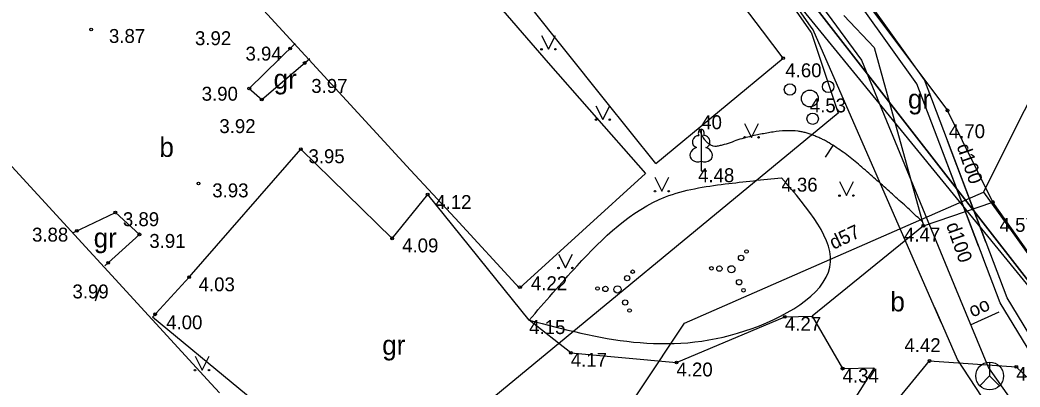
# Model space of a CAD drawing. Extents: x 519536 to 519949, y 326041 to 326519.
# Drawn here: x 519801.93 to 519837.87, y 326233.27 to 326246.46 of the extents above; entities that cross this region are included whole.
import ezdxf

# ---------------------------------------------------------------- set-up
doc = ezdxf.new("R2010")
doc.units = 0
for name, color, linetype in [('APGR_SARK_####_####_#', 7, 'Continuous'), ('BUVE_EKAS_####_####_#', 7, 'Continuous'), ('CELI_CMAL_####_####_#', 7, 'Continuous'), ('CELI_CSEG_####_TKST_#', 7, 'Continuous'), ('CELI_SEGL_####_####_#', 7, 'Continuous'), ('ELEK_ACRL_####_####_#', 7, 'Continuous'), ('ELEK_ACRL_####_TKST_#', 7, 'Continuous'), ('ELEK_VADP_ZSPR_####_#', 7, 'Continuous'), ('GAZE_VADP_ASP1_####_#', 7, 'Continuous'), ('GAZE_VADP_NEDR_####_#', 7, 'Continuous'), ('GAZE_VADP_NEDR_TKST_#', 7, 'Continuous'), ('RELJ_AATZ_####_TKST_#', 7, 'Continuous'), ('RELJ_ELEM_####_####_#', 7, 'Continuous'), ('RELJ_HORZ_PAMT_####_#', 7, 'Continuous'), ('ROBZ_PROJ_####_####_#', 7, 'Continuous'), ('ROBZ_UZMR_####_####_#', 7, 'Continuous'), ('SAKK_ELEM_####_####_#', 7, 'Continuous'), ('SAKK_IZVK_####_TKST_#', 7, 'Continuous'), ('SAKK_KKAN_####_####_#', 7, 'Continuous'), ('TERT_DIAM_####_TKST_#', 7, 'Continuous'), ('TERT_ELEM_####_####_#', 7, 'Continuous'), ('TERT_KONT_####_####_#', 7, 'Continuous')]:
    doc.layers.add(name, color=color, linetype=linetype)

msp = doc.modelspace()

# ---------------------------------------------------------------- linework, layer by layer
at = {"layer": 'APGR_SARK_####_####_#'}
msp.add_line((519771.502, 326318.577), (519839.505, 326235.263), dxfattribs=at)
at = {"layer": 'BUVE_EKAS_####_####_#'}
msp.add_line((519819.879, 326236.819), (519824.406, 326240.947), dxfattribs=at)
for points in [[(519815.97, 326241.067), (519794.322, 326264.64), (519799.853, 326269.244)], [(519799.853, 326269.244), (519820.912, 326244.923)], [(519821.513, 326245.392), (519802.904, 326268.709)], [(519808.8, 326233.381), (519787.845, 326256.231), (519782.307, 326251.018)], [(519828.616, 326246.073), (519826.305, 326249.13)], [(519824.78, 326241.299), (519829.361, 326245.088), (519828.616, 326246.073)], [(519822.941, 326243.604), (519821.513, 326245.392)], [(519820.912, 326244.923), (519822.387, 326243.244)], [(519824.78, 326241.299), (519822.941, 326243.604)], [(519822.387, 326243.244), (519824.406, 326240.947)], [(519817.566, 326239.333), (519815.97, 326241.067)], [(519819.879, 326236.819), (519817.566, 326239.333)], [(519809.102, 326233.051), (519808.8, 326233.381)]]:
    msp.add_lwpolyline(points, dxfattribs=at)
at = {"layer": 'CELI_CMAL_####_####_#'}
for p, q in [((519831.546, 326246.618), (519832.626, 326245.477)), ((519811.824, 326245.617), (519810.171, 326243.995)), ((519810.617, 326243.606), (519812.348, 326245.072)), ((519810.171, 326243.995), (519810.617, 326243.606)), ((519808.01, 326237.212), (519812.026, 326241.818)), ((519812.026, 326241.818), (519815.308, 326238.61)), ((519815.308, 326238.61), (519816.583, 326240.187)), ((519803.858, 326238.824), (519805.357, 326239.536)), ((519805.357, 326239.536), (519806.221, 326238.754)), ((519806.221, 326238.754), (519804.98, 326237.626)), ((519806.695, 326235.774), (519808.01, 326237.212))]:
    msp.add_line(p, q, dxfattribs=at)
for points in [[(519797.68, 326294.786), (519803.307, 326287.694), (519809.593, 326279.318), (519814.875, 326272.28), (519822.676, 326261.61), (519829.759, 326251.994), (519832.548, 326246.837), (519835.264, 326243.212)], [(519832.626, 326245.477), (519834.4, 326239.065)], [(519882.222, 326178.789), (519878.977, 326182.88), (519874.995, 326188.433), (519867.888, 326197.765), (519858.139, 326210.779), (519849.58, 326222.15), (519841.494, 326233.418), (519836.895, 326239.916), (519835.264, 326243.212)], [(519821.726, 326234.491), (519820.231, 326235.669), (519816.583, 326240.187)], [(519834.4, 326239.065), (519830.403, 326235.818), (519831.497, 326233.926), (519832.631, 326233.959), (519830.408, 326230.433), (519831.453, 326230.348), (519834.622, 326234.201), (519837.739, 326233.988), (519838.727, 326233.045), (519840.51, 326232.736), (519841.494, 326233.418)], [(519802.986, 326218.602), (519812.095, 326226.609), (519812.9, 326230.644), (519806.695, 326235.774)], [(519821.726, 326234.491), (519825.526, 326234.144), (519829.423, 326235.788), (519830.403, 326235.818)]]:
    msp.add_lwpolyline(points, dxfattribs=at)
at = {"layer": 'CELI_SEGL_####_####_#'}
msp.add_lwpolyline([(519834.4, 326239.065), (519836.895, 326239.916)], dxfattribs=at)
at = {"layer": 'ELEK_ACRL_####_####_#'}
for p, q in [((519834.982, 326242.008), (519836.373, 326238.339)), ((519836.644, 326238.468), (519835.262, 326242.12))]:
    msp.add_line(p, q, dxfattribs=at)
at = {"layer": 'ELEK_VADP_ZSPR_####_#'}
for points in [[(519830.369, 326246.03), (519828.17, 326249.181), (519802.207, 326283.896), (519795.993, 326292.283), (519770.741, 326312.416), (519767.549, 326319.699), (519768.203, 326324.348), (519772.317, 326338.857)], [(519830.345, 326246.245), (519827.61, 326250.148)], [(519836.543, 326237.909), (519834.17, 326244.171), (519832.235, 326246.864)], [(519836.785, 326238.116), (519834.436, 326244.315), (519832.53, 326246.969)], [(519835.04, 326235.585), (519830.444, 326246.104), (519830.345, 326246.245)], [(519830.369, 326246.03), (519831.331, 326243.11), (519817.596, 326231.779), (519823.495, 326223.549)], [(519858.442, 326207.088), (519839.697, 326232.115), (519837.156, 326236.293), (519836.532, 326237.937)], [(519858.585, 326207.398), (519839.95, 326232.294), (519837.409, 326236.472), (519836.785, 326238.116)], [(519842.423, 326223.872), (519835.623, 326234.253), (519834.808, 326236.118)]]:
    msp.add_lwpolyline(points, dxfattribs=at)
at = {"layer": 'GAZE_VADP_ASP1_####_#'}
for p, q in [((519836.566, 326240.266), (519837.552, 326238.889)), ((519837.552, 326238.889), (519853.45, 326216.69))]:
    msp.add_line(p, q, dxfattribs=at)
msp.add_lwpolyline([(519836.553, 326240.247), (519839.519, 326246.171)], dxfattribs=at)
at = {"layer": 'GAZE_VADP_NEDR_####_#'}
msp.add_lwpolyline([(519819.823, 326209.512), (519817.948, 326223.716), (519825.819, 326235.566), (519836.566, 326240.266)], dxfattribs=at)
at = {"layer": 'RELJ_ELEM_####_####_#'}
for centre in [(519804.486, 326246.116), (519811.641, 326245.438), (519829.361, 326245.088), (519812.163, 326244.915), (519810.171, 326243.995), (519810.617, 326243.606), (519835.264, 326243.212), (519812.026, 326241.818), (519808.342, 326240.585), (519816.583, 326240.187), (519836.895, 326239.916), (519805.357, 326239.536), (519803.97, 326238.877), (519834.4, 326239.065), (519806.221, 326238.754), (519815.308, 326238.61), (519805.096, 326237.731), (519808.01, 326237.212), (519819.902, 326236.854), (519806.791, 326235.879), (519829.423, 326235.788), (519821.726, 326234.491), (519834.622, 326234.201), (519825.526, 326234.144), (519831.497, 326233.926), (519837.739, 326233.988)]:
    msp.add_circle(centre, 0.05, dxfattribs=at)
at = {"layer": 'RELJ_HORZ_PAMT_####_#'}
for p, q in [((519830.882, 326241.533), (519831.152, 326241.954)), ((519804.638, 326236.365), (519804.803, 326236.837))]:
    msp.add_line(p, q, dxfattribs=at)
msp.add_spline([(519834.359, 326239.213), (519833.956, 326239.589), (519833.474, 326240.03), (519832.988, 326240.466), (519832.498, 326240.899), (519832.004, 326241.328), (519831.767, 326241.522), (519831.522, 326241.704), (519831.269, 326241.877), (519831.01, 326242.043), (519830.879, 326242.119), (519830.745, 326242.186), (519830.608, 326242.247), (519830.467, 326242.305), (519830.327, 326242.357), (519830.186, 326242.402), (519830.043, 326242.437), (519829.898, 326242.461), (519829.447, 326242.48), (519828.998, 326242.434), (519828.771, 326242.395), (519828.545, 326242.352), (519828.32, 326242.305), (519828.095, 326242.251), (519827.807, 326242.171), (519827.523, 326242.074), (519827.239, 326241.981), (519827.098, 326241.944), (519826.956, 326241.918), (519826.843, 326241.928), (519826.787, 326241.949), (519826.732, 326241.978), (519826.678, 326242.015), (519826.63, 326242.059), (519826.542, 326242.157), (519826.459, 326242.288), (519826.395, 326242.425), (519826.327, 326242.578)], degree=3, dxfattribs=at)
at = {"layer": 'ROBZ_PROJ_####_####_#'}
msp.add_line((519841.088, 326233.318), (519793.426, 326294.677), dxfattribs=at)
at = {"layer": 'ROBZ_UZMR_####_####_#'}
msp.add_line((519793.426, 326294.677), (519841.088, 326233.318), dxfattribs=at)
at = {"layer": 'SAKK_ELEM_####_####_#'}
msp.add_line((519836.781, 326233.661), (519837.135, 326233.307), dxfattribs=at)
msp.add_lwpolyline([(519836.781, 326234.161), (519836.781, 326233.661), (519836.427, 326233.307)], dxfattribs=at)
msp.add_circle((519836.781, 326233.661), 0.5, dxfattribs=at)
at = {"layer": 'SAKK_IZVK_####_TKST_#'}
msp.add_line((519836.099, 326235.503), (519837.127, 326235.971), dxfattribs=at)
at = {"layer": 'SAKK_KKAN_####_####_#'}
for points in [[(519828.098, 326250.529), (519831.106, 326246.462)], [(519831.106, 326246.462), (519832.172, 326245.02), (519835.663, 326236.557)], [(519835.52, 326236.905), (519836.738, 326233.953), (519845.772, 326221.145), (519858.019, 326204.182), (519864.377, 326195.733)]]:
    msp.add_lwpolyline(points, dxfattribs=at)
at = {"layer": 'TERT_ELEM_####_####_#'}
for p, q in [((519820.676, 326245.91), (519820.926, 326245.41)), ((519820.926, 326245.41), (519821.176, 326245.91)), ((519822.629, 326243.38), (519822.879, 326242.88)), ((519822.879, 326242.88), (519823.129, 326243.38)), ((519827.975, 326242.742), (519828.225, 326242.242)), ((519828.225, 326242.242), (519828.475, 326242.742)), ((519826.415, 326241.382), (519826.415, 326241.035)), ((519824.75, 326240.805), (519825, 326240.305)), ((519825, 326240.305), (519825.25, 326240.805)), ((519826.415, 326241.035), (519826.615, 326241.035)), ((519831.385, 326240.65), (519831.635, 326240.15)), ((519831.635, 326240.15), (519831.885, 326240.65)), ((519821.286, 326238.045), (519821.536, 326237.545)), ((519821.536, 326237.545), (519821.786, 326238.045)), ((519808.224, 326234.373), (519808.474, 326233.873)), ((519808.474, 326233.873), (519808.724, 326234.373))]:
    msp.add_line(p, q, dxfattribs=at)
for points in [[(519826.415, 326242.535), (519826.415, 326241.382)], [(519826.505, 326242.303), (519826.504, 326242.304)]]:
    msp.add_lwpolyline(points, dxfattribs=at)
for centre, radius in [((519820.675, 326245.41), 0.028), ((519821.175, 326245.41), 0.0263), ((519829.604, 326243.962), 0.204), ((519830.98, 326244.063), 0.207), ((519830.318, 326243.639), 0.301), ((519822.629, 326242.879), 0.028), ((519823.129, 326242.879), 0.0263), ((519830.421, 326242.911), 0.205), ((519827.975, 326242.242), 0.028), ((519828.475, 326242.242), 0.0263), ((519824.75, 326240.305), 0.028), ((519825.25, 326240.305), 0.0263), ((519831.385, 326240.149), 0.028), ((519831.885, 326240.149), 0.0263), ((519828.044, 326238.139), 0.064), ((519827.848, 326237.908), 0.096), ((519821.285, 326237.545), 0.028), ((519821.785, 326237.545), 0.0263), ((519826.782, 326237.534), 0.064), ((519827.066, 326237.521), 0.096), ((519827.5, 326237.5), 0.128), ((519823.753, 326237.18), 0.096), ((519823.95, 326237.411), 0.064), ((519827.776, 326237.033), 0.096), ((519822.687, 326236.806), 0.064), ((519822.972, 326236.793), 0.096), ((519823.406, 326236.772), 0.128), ((519827.934, 326236.744), 0.064), ((519823.682, 326236.305), 0.096), ((519823.84, 326236.016), 0.064), ((519808.223, 326233.872), 0.028), ((519808.723, 326233.872), 0.0263)]:
    msp.add_circle(centre, radius, dxfattribs=at)
for centre, major_axis, ratio, start_param, end_param in [((519826.415, 326242.385), (0, -0.15), 0.707107, 3.14537, 5.287485), ((519826.415, 326242.385), (0, -0.15), 0.707107, 0.995701, 3.137816), ((519826.287, 326242.09), (-0.039, -0.212), 0.861323, 3.141593, 6.283185), ((519826.543, 326242.09), (0.039, -0.212), 0.861323, 0, 3.141593), ((519826.325, 326241.628), (0.307, 0.095), 0.814445, 1.570796, 4.752015), ((519826.505, 326241.628), (-0.307, 0.095), 0.814445, 1.531171, 4.712389)]:
    msp.add_ellipse(centre, major_axis=major_axis, ratio=ratio, start_param=start_param, end_param=end_param, dxfattribs=at)
at = {"layer": 'TERT_KONT_####_####_#'}
for points in [[(519820.231, 326235.669), (519827.986, 326235.279), (519831.04, 326237.579), (519829.297, 326240.791)], [(519820.231, 326235.669), (519821.955, 326237.623), (519825.127, 326240.1), (519827.274, 326240.565), (519829.297, 326240.791)]]:
    msp.add_spline(points, degree=3, dxfattribs=at)

# ---------------------------------------------------------------- texts
at = {"layer": 'CELI_CSEG_####_TKST_#'}
for s, p in [('gr', (519811.045, 326243.989)), ('gr', (519833.847, 326243.272)), ('b', (519806.941, 326241.539)), ('gr', (519804.579, 326238.281)), ('b', (519833.214, 326235.985)), ('gr', (519814.949, 326234.424))]:
    msp.add_text(s, height=0.7, dxfattribs=at).set_placement(p)
at = {"layer": 'ELEK_ACRL_####_TKST_#'}
for rotation, p in [(289.0794, (519835.589, 326241.924)), (289.4231, (519835.21, 326239.092))]:
    msp.add_text('d100', height=0.5, rotation=rotation, dxfattribs=at).set_placement(p)
at = {"layer": 'GAZE_VADP_NEDR_TKST_#'}
msp.add_text(' d57', height=0.5, rotation=25.6904, dxfattribs=at).set_placement((519831.004, 326238.115))
at = {"layer": 'RELJ_AATZ_####_TKST_#'}
for s, p in [('3.87', (519805.128, 326245.637)), ('3.92', (519808.22, 326245.557)), ('3.94', (519810.034, 326245.003)), ('4.60', (519829.438, 326244.403)), ('3.97', (519812.399, 326243.841)), ('3.90', (519808.461, 326243.56)), ('4.53', (519830.318, 326243.139)), ('3.92', (519809.096, 326242.395)), ('4.70', (519835.314, 326242.212)), ('3.95', (519812.298, 326241.313)), ('4.48', (519826.302, 326240.63)), ('4.36', (519829.297, 326240.291)), ('3.93', (519808.842, 326240.085)), ('4.12', (519816.855, 326239.666)), ('3.89', (519805.629, 326239.049)), ('4.57', (519837.139, 326238.845)), ('3.88', (519802.363, 326238.494)), ('4.47', (519833.704, 326238.496)), ('3.91', (519806.579, 326238.267)), ('4.09', (519815.666, 326238.106)), ('4.03', (519808.35, 326236.707)), ('4.22', (519820.295, 326236.747)), ('3.99', (519803.816, 326236.451)), ('4.00', (519807.184, 326235.34)), ('4.27', (519829.423, 326235.288)), ('4.15', (519820.231, 326235.169)), ('4.42', (519833.719, 326234.518)), ('4.17', (519821.726, 326233.991)), ('4.20', (519825.526, 326233.644)), ('4.34', (519831.497, 326233.426)), ('4.48', (519837.739, 326233.488))]:
    msp.add_text(s, height=0.5, dxfattribs=at).set_placement(p)
at = {"layer": 'SAKK_IZVK_####_TKST_#'}
msp.add_text('oo', height=0.5, rotation=24.4704, dxfattribs=at).set_placement((519836.164, 326235.758))
at = {"layer": 'TERT_DIAM_####_TKST_#'}
msp.add_text('40', height=0.5, dxfattribs=at).set_placement((519826.415, 326242.535))

doc.saveas('drawing.dxf')
